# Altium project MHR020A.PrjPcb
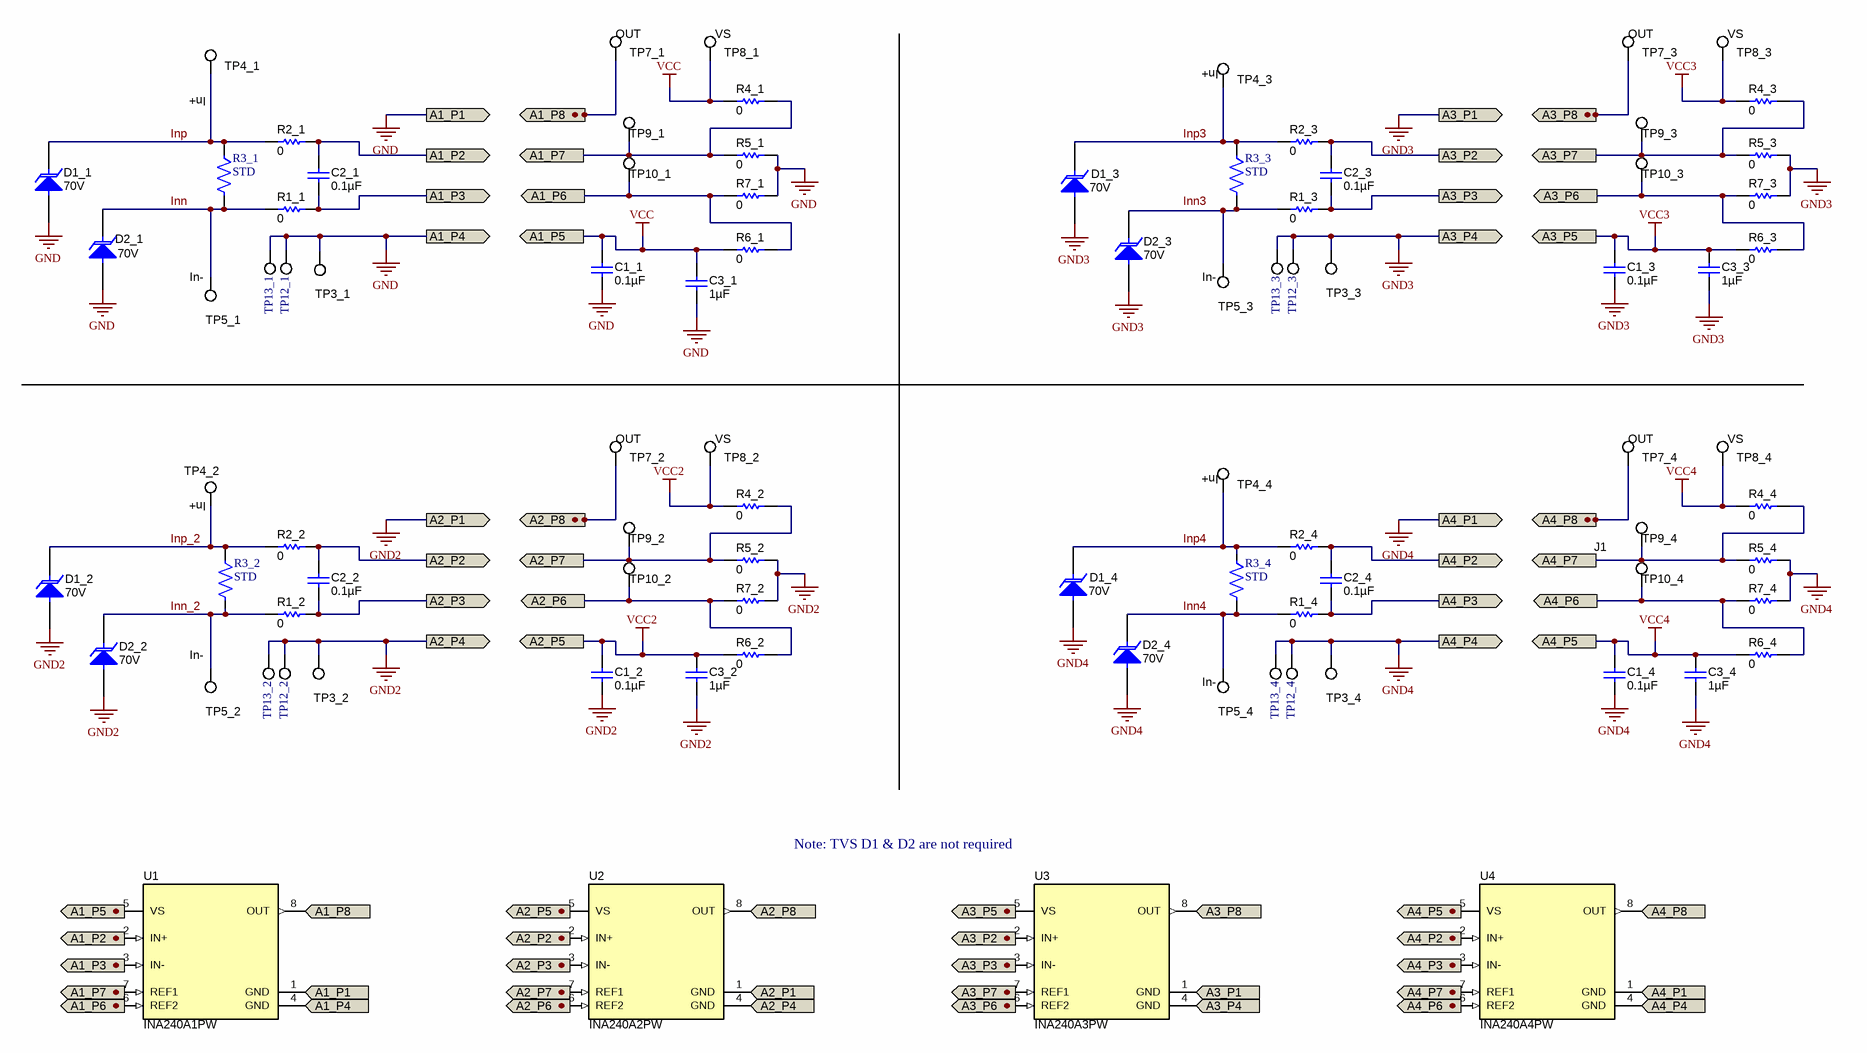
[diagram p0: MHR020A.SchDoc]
CopyrightYear: 2016; PCB_Layout: Guang Zhou; PCB_Rev: B; PRJ_Customer: Public; PRJ_Engineer: Guang Zhou; PRJ_Number: MHR020; PRJ_Title: INA240EVM; SCH_Rev: A; TechSupport: http://www.ti.com/support; TID: N/A
2 sheets, 119 parts. Net scope: flat (ports and power ports of the same name join across sheets).
Board file: MHR020B.PcbDoc
Sheets:
  MHR020A.SchDoc
  MHR020A_Hardware.SchDoc

## Sheet MHR020A.SchDoc: Schematic
size 431 x 279 mm; Date: Not shown in title block; ApprovedBy: Not shown in title block; CheckedBy: Not shown in title block; Author: Not shown in title block; CompanyName: Not shown in title block; DrawnBy: Guang Zhou; Engineer: Not shown in title block; Organization: Not shown in title block; Address1: Not shown in title block; Address2: Not shown in title block; Address3: Not shown in title block; Address4: Not shown in title block; DocumentNumber: 1; Revision: Use project parameter SCH_Rev; SheetNumber: 2; SheetTotal: 3; PageSetup: Record=PageOptions¦CenterHorizontal=True¦CenterVertical=True¦PrintScale=1.00¦XCorrection=1.00¦YCorrection=1.00¦PrintKind=0¦BorderSize=5000000¦LeftOffset=0¦BottomOffset=0¦Orientation=2¦PaperLength=1000¦PaperWidth=1000¦Scale=100¦PaperSource=15¦PrintQuality=600¦MediaType=1¦DitherType=10¦PaperKind=Letter¦PrintScaleMode=1

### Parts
C1_1  ValueDisplayed: 0.1µF  [0603]  (hidden comment: 0603YC104JAT2A)
C1_2  ValueDisplayed: 0.1µF  [0603]  (hidden comment: 0603YC104JAT2A)
C1_3  ValueDisplayed: 0.1µF  [0603]  (hidden comment: 0603YC104JAT2A)
C1_4  ValueDisplayed: 0.1µF  [0603]  (hidden comment: 0603YC104JAT2A)
C2_1  ValueDisplayed: 0.1µF  [0603]  (hidden comment: 0603YC104JAT2A)
C2_2  ValueDisplayed: 0.1µF  [0603]  (hidden comment: 0603YC104JAT2A)
C2_3  ValueDisplayed: 0.1µF  [0603]  (hidden comment: 0603YC104JAT2A)
C2_4  ValueDisplayed: 0.1µF  [0603]  (hidden comment: 0603YC104JAT2A)
C3_1  ValueDisplayed: 1µF  [0805_HV]  (hidden comment: 08053D105KAT2A)
C3_2  ValueDisplayed: 1µF  [0805_HV]  (hidden comment: 08053D105KAT2A)
C3_3  ValueDisplayed: 1µF  [0805_HV]  (hidden comment: 08053D105KAT2A)
C3_4  ValueDisplayed: 1µF  [0805_HV]  (hidden comment: 08053D105KAT2A)
D1_1  value 70V  [SMB]  (hidden comment: SMBJ70A-13-F)
D1_2  value 70V  [SMB]  (hidden comment: SMBJ70A-13-F)
D1_3  value 70V  [SMB]  (hidden comment: SMBJ70A-13-F)
D1_4  value 70V  [SMB]  (hidden comment: SMBJ70A-13-F)
D2_1  value 70V  [SMB]  (hidden comment: SMBJ70A-13-F)
D2_2  value 70V  [SMB]  (hidden comment: SMBJ70A-13-F)
D2_3  value 70V  [SMB]  (hidden comment: SMBJ70A-13-F)
D2_4  value 70V  [SMB]  (hidden comment: SMBJ70A-13-F)
R1_1  ValueDisplayed: 0  [0603]  (hidden comment: ERJ-3GEY0R00V)
R1_2  ValueDisplayed: 0  [0603]  (hidden comment: ERJ-3GEY0R00V)
R1_3  ValueDisplayed: 0  [0603]  (hidden comment: ERJ-3GEY0R00V)
R1_4  ValueDisplayed: 0  [0603]  (hidden comment: ERJ-3GEY0R00V)
R2_1  ValueDisplayed: 0  [0603]  (hidden comment: ERJ-3GEY0R00V)
R2_2  ValueDisplayed: 0  [0603]  (hidden comment: ERJ-3GEY0R00V)
R2_3  ValueDisplayed: 0  [0603]  (hidden comment: ERJ-3GEY0R00V)
R2_4  ValueDisplayed: 0  [0603]  (hidden comment: ERJ-3GEY0R00V)
R3_1  STD  [R2512]
R3_2  STD  [R2512]
R3_3  STD  [R2512]
R3_4  STD  [R2512]
R4_1  ValueDisplayed: 0  [0603]  (hidden comment: ERJ-3GEY0R00V)
R4_2  ValueDisplayed: 0  [0603]  (hidden comment: ERJ-3GEY0R00V)
R4_3  ValueDisplayed: 0  [0603]  (hidden comment: ERJ-3GEY0R00V)
R4_4  ValueDisplayed: 0  [0603]  (hidden comment: ERJ-3GEY0R00V)
R5_1  ValueDisplayed: 0  [0603]  (hidden comment: ERJ-3GEY0R00V)
R5_2  ValueDisplayed: 0  [0603]  (hidden comment: ERJ-3GEY0R00V)
R5_3  ValueDisplayed: 0  [0603]  (hidden comment: ERJ-3GEY0R00V)
R5_4  ValueDisplayed: 0  [0603]  (hidden comment: ERJ-3GEY0R00V)
R6_1  ValueDisplayed: 0  [0603]  (hidden comment: ERJ-3GEY0R00V)
R6_2  ValueDisplayed: 0  [0603]  (hidden comment: ERJ-3GEY0R00V)
R6_3  ValueDisplayed: 0  [0603]  (hidden comment: ERJ-3GEY0R00V)
R6_4  ValueDisplayed: 0  [0603]  (hidden comment: ERJ-3GEY0R00V)
R7_1  ValueDisplayed: 0  [0603]  (hidden comment: ERJ-3GEY0R00V)
R7_2  ValueDisplayed: 0  [0603]  (hidden comment: ERJ-3GEY0R00V)
R7_3  ValueDisplayed: 0  [0603]  (hidden comment: ERJ-3GEY0R00V)
R7_4  ValueDisplayed: 0  [0603]  (hidden comment: ERJ-3GEY0R00V)
TP3_1  5012  [Keystone5012]  (value not drawn)
TP3_2  5012  [Keystone5012]  (value not drawn)
TP3_3  5012  [Keystone5012]  (value not drawn)
TP3_4  5012  [Keystone5012]  (value not drawn)
TP4_1  5012  [Keystone5012]  (value not drawn)
TP4_2  5012  [Keystone5012]  (value not drawn)
TP4_3  5012  [Keystone5012]  (value not drawn)
TP4_4  5012  [Keystone5012]  (value not drawn)
TP5_1  5012  [Keystone5012]  (value not drawn)
TP5_2  5012  [Keystone5012]  (value not drawn)
TP5_3  5012  [Keystone5012]  (value not drawn)
TP5_4  5012  [Keystone5012]  (value not drawn)
TP7_1  5012  [Keystone5012]  (value not drawn)
TP7_2  5012  [Keystone5012]  (value not drawn)
TP7_3  5012  [Keystone5012]  (value not drawn)
TP7_4  5012  [Keystone5012]  (value not drawn)
TP8_1  5012  [Keystone5012]  (value not drawn)
TP8_2  5012  [Keystone5012]  (value not drawn)
TP8_3  5012  [Keystone5012]  (value not drawn)
TP8_4  5012  [Keystone5012]  (value not drawn)
TP9_1  5012  [Keystone5012]  (value not drawn)
TP9_2  5012  [Keystone5012]  (value not drawn)
TP9_3  5012  [Keystone5012]  (value not drawn)
TP9_4  5012  [Keystone5012]  (value not drawn)
TP10_1  5012  [Keystone5012]  (value not drawn)
TP10_2  5012  [Keystone5012]  (value not drawn)
TP10_3  5012  [Keystone5012]  (value not drawn)
TP10_4  5012  [Keystone5012]  (value not drawn)
TP12_1  5012  [Keystone5012]  (value not drawn)
TP12_2  5012  [Keystone5012]  (value not drawn)
TP12_3  5012  [Keystone5012]  (value not drawn)
TP12_4  5012  [Keystone5012]  (value not drawn)
TP13_1  5012  [Keystone5012]  (value not drawn)
TP13_2  5012  [Keystone5012]  (value not drawn)
TP13_3  5012  [Keystone5012]  (value not drawn)
TP13_4  5012  [Keystone5012]  (value not drawn)
U1  INA240A1PW  [PW0008A_N]
U2  INA240A2PW  [PW0008A_N]
U3  INA240A3PW  [PW0008A_N]
U4  INA240A4PW  [PW0008A_N]

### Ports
A1_P1 (in), A1_P1 (out), A1_P2 (in), A1_P2 (out), A1_P3 (in), A1_P3 (out), A1_P4 (in), A1_P4 (out), A1_P5 (in), A1_P5 (out), A1_P6 (in), A1_P6 (out), A1_P7 (in), A1_P7 (out), A1_P8 (in), A1_P8 (out), A2_P1 (in), A2_P1 (out), A2_P2 (in), A2_P2 (out), A2_P3 (in), A2_P3 (out), A2_P4 (in), A2_P4 (out), A2_P5 (in), A2_P5 (out), A2_P6 (in), A2_P6 (out), A2_P7 (in), A2_P7 (out), A2_P8 (in), A2_P8 (out), A3_P1 (in), A3_P1 (out), A3_P2 (in), A3_P2 (out), A3_P3 (in), A3_P3 (out), A3_P4 (in), A3_P4 (out), A3_P5 (in), A3_P5 (out), A3_P6 (in), A3_P6 (out), A3_P7 (in), A3_P7 (out), A3_P8 (in), A3_P8 (out), A4_P1 (in), A4_P1 (out), A4_P2 (in), A4_P2 (out), A4_P3 (in), A4_P3 (out), A4_P4 (in), A4_P4 (out), A4_P5 (in), A4_P5 (out), A4_P6 (in), A4_P6 (out), A4_P7 (in), A4_P7 (out), A4_P8 (in), A4_P8 (out)

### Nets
GND: C1_1.2 C3_1.2 D1_1.2(A) D2_1.2(A) R5_1.2 R7_1.2 TP3_1.1 TP12_1.1 TP13_1.1 U1.1(GND) U1.4(GND) ; port A1_P1, port A1_P4
GND2: C1_2.2 C3_2.2 D1_2.2(A) D2_2.2(A) R5_2.2 R7_2.2 TP3_2.1 TP12_2.1 TP13_2.1 U2.1(GND) U2.4(GND) ; port A2_P1, port A2_P4
GND3: C1_3.2 C3_3.2 D1_3.2(A) D2_3.2(A) R5_3.2 R7_3.2 TP3_3.1 TP12_3.1 TP13_3.1 U3.1(GND) U3.4(GND) ; port A3_P1, port A3_P4
GND4: C1_4.2 C3_4.2 D1_4.2(A) D2_4.2(A) R5_4.2 R7_4.2 TP3_4.1 TP12_4.1 TP13_4.1 U4.1(GND) U4.4(GND) ; port A4_P1, port A4_P4
VCC: C1_1.1 C3_1.1 R4_1.1 R6_1.1 TP8_1.1 ; port A1_P5
VCC2: C1_2.1 C3_2.1 R4_2.1 R6_2.1 TP8_2.1 ; port A2_P5
VCC3: C1_3.1 C3_3.1 R4_3.1 R6_3.1 TP8_3.1 ; port A3_P5
VCC4: C1_4.1 C3_4.1 R4_4.1 R6_4.1 TP8_4.1 ; port A4_P5
A1_P2: C2_1.2 R2_1.2 ; port A1_P2
A1_P3: C2_1.1 R1_1.2 ; port A1_P3
A1_P6: R6_1.2 R7_1.1 TP10_1.1 ; port A1_P6
A1_P7: R4_1.2 R5_1.1 TP9_1.1 ; port A1_P7
A1_P8: TP7_1.1 U1.8(OUT) ; port A1_P8
A2_P2: C2_2.2 R2_2.2 ; port A2_P2
A2_P3: C2_2.1 R1_2.2 ; port A2_P3
A2_P6: R6_2.2 R7_2.1 TP10_2.1 ; port A2_P6
A2_P7: R4_2.2 R5_2.1 TP9_2.1 ; port A2_P7
A2_P8: TP7_2.1 U2.8(OUT) ; port A2_P8
A3_P2: C2_3.2 R2_3.2 ; port A3_P2
A3_P3: C2_3.1 R1_3.2 ; port A3_P3
A3_P6: R6_3.2 R7_3.1 TP10_3.1 ; port A3_P6
A3_P7: R4_3.2 R5_3.1 TP9_3.1 ; port A3_P7
A3_P8: TP7_3.1 U3.8(OUT) ; port A3_P8
A4_P2: C2_4.2 R2_4.2 ; port A4_P2
A4_P3: C2_4.1 R1_4.2 ; port A4_P3
A4_P6: R6_4.2 R7_4.1 TP10_4.1 ; port A4_P6
A4_P7: R4_4.2 R5_4.1 TP9_4.1 ; port A4_P7
A4_P8: TP7_4.1 U4.8(OUT) ; port A4_P8
Inn: D2_1.1(K) R1_1.1 R3_1.2 TP5_1.1
Inn4: D2_4.1(K) R1_4.1 R3_4.2 TP5_4.1
Inn_2: D2_2.1(K) R1_2.1 R3_2.2 TP5_2.1
Inp: D1_1.1(K) R2_1.1 R3_1.1 TP4_1.1
Inp3: D1_3.1(K) R2_3.1 R3_3.1 TP4_3.1
Inp4: D1_4.1(K) R2_4.1 R3_4.1 TP4_4.1
Inp_2: D1_2.1(K) R2_2.1 R3_2.1 TP4_2.1
NetD2_3_1: D2_3.1(K) R1_3.1 R3_3.2 TP5_3.1

Not connected (* = marked no-connect by the designer): U1 2(IN+) 3(IN-) 5(VS) 6(REF2) 7(REF1); U2 2(IN+) 3(IN-) 5(VS) 6(REF2) 7(REF1); U3 2(IN+) 3(IN-) 5(VS) 6(REF2) 7(REF1); U4 2(IN+) 3(IN-) 5(VS) 6(REF2) 7(REF1)

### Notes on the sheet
- (near TP7_1) OUT
- (near TP8_1) VS
- (near TP4_3) In+
- (near TP7_3) OUT
- (near TP8_3) VS
- In+
- (near TP5_1) In-
- (near TP5_3) In-
- (near TP7_2) OUT
- (near TP8_2) VS
- (near TP4_4) In+
- (near TP7_4) OUT
- (near TP8_4) VS
- (near TP4_2) In+
- J1
- (near TP5_2) In-
- (near TP5_4) In-
- Note: TVS D1 & D2 are not required
- Labels drawn without touching a wire or pin: Inn3

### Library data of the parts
C1_1-C1_4 C2_1-C2_4 = 0603YC104JAT2A: CAP, CERM, 0.1 µF, 16 V, +/- 5%, X7R, 0603; Manufacturer: AVX; Polarized: N; CompType: Capacitor; Value: 0.1uF; U/M: EA; Cap_F: 0.0000001; Tolerance_%: 5; ESR_ohm: 0.039; Value1: 0.039 ohm; VDC_V: 16; Value2: 16V; TaMin_C: -55; TaMax_C: 125
C3_1-C3_4 = 08053D105KAT2A: CAP, CERM, 1 µF, 25 V, +/- 10%, X5R, 0805; Manufacturer: AVX; Polarized: N; CompType: Capacitor; Value: 1uF; U/M: EA; Cap_F: 0.000001; Tolerance_%: 10; ESR_ohm: 0.012; Value1: 0.012 ohm; VDC_V: 25; Value2: 25V; TaMin_C: -55; TaMax_C: 85; Cap_Case: 0805; AEC Category: Q200
D1_1-D1_4 D2_1-D2_4 = SMBJ70A-13-F: Diode, TVS, Uni, 70 V, 600 W, SMB; Manufacturer: Diodes Inc.; U/M: EA; Power_W: 5; Vr_V: 70; Value1: 5W; AEC Category: Q101
R1_1-R1_4 R2_1-R2_4 R4_1-R4_4 R5_1-R5_4 R6_1-R6_4 R7_1-R7_4 = ERJ-3GEY0R00V: RES, 0, 5%, 0.1 W, 0603; Manufacturer: Panasonic; CompType: Resistor; Value: 0; Value_Code: 0000; Tolerance_%: 5; Power_W: 0.1; Value2: 0.1W; VDC_V: 50; TempCo: 600 ppm/C; EIA_Code: E24; U/M: EA; AEC Category: Q200
R3_1-R3_4 = R2512: Resistor,  xx milliOhm, 1W, yy%; Area: 35100; Value: {Value}
TP3_1-TP3_4 TP4_1-TP4_4 TP5_1-TP5_4 TP7_1-TP7_4 TP8_1-TP8_4 TP9_1-TP9_4 TP10_1-TP10_4 = 5012: Test Point, Multipurpose, White, TH; Manufacturer: Keystone; CompType: Test Point Loop; U/M: EA
TP12_1-TP12_4 TP13_1-TP13_4 = 5012: Test Point, Multipurpose, White, TH; Manufacturer: Keystone; CompType: Test Point Loop; ContactFinish: Silver
U1 = INA240A1PW: Wide Common-Mode Range, Voltage Output, High or Low-Side Bi-Directional Zero-Drift Current Shunt Monitor, PW0008A; Manufacturer: Texas Instruments; SymbolCreator: Altium; CompType: IC; U/M: EA
U2 = INA240A2PW: Wide Common-Mode Range, Voltage Output, High or Low-Side Bi-Directional Zero-Drift Current Shunt Monitor, PW0008A; Manufacturer: Texas Instruments; SymbolCreator: Altium; CompType: IC; U/M: EA
U3 = INA240A3PW: Wide Common-Mode Range, Voltage Output, High or Low-Side Bi-Directional Zero-Drift Current Shunt Monitor, PW0008A; Manufacturer: Texas Instruments; SymbolCreator: Altium; CompType: IC; U/M: EA
U4 = INA240A4PW: Wide Common-Mode Range, Voltage Output, High or Low-Side Bi-Directional Zero-Drift Current Shunt Monitor, PW0008A; Manufacturer: Texas Instruments; SymbolCreator: Altium; CompType: IC; U/M: EA

## Sheet MHR020A_Hardware.SchDoc: Hardware
size 431 x 279 mm; Date: Not shown in title block; ApprovedBy: Not shown in title block; CheckedBy: Not shown in title block; Author: Not shown in title block; CompanyName: Not shown in title block; DrawnBy: Guang Zhou; Engineer: Not shown in title block; Organization: Not shown in title block; Address1: Not shown in title block; Address2: Not shown in title block; Address3: Not shown in title block; Address4: Not shown in title block; DocumentNumber: 1; Revision: Use project parameter SCH_Rev; SheetNumber: 3; SheetTotal: 3; PageSetup: Record=PageOptions¦CenterHorizontal=True¦CenterVertical=True¦PrintScale=1.00¦XCorrection=1.00¦YCorrection=1.00¦PrintKind=0¦BorderSize=5000000¦LeftOffset=0¦BottomOffset=0¦Orientation=2¦PaperLength=1000¦PaperWidth=1000¦Scale=100¦PaperSource=15¦PrintQuality=600¦MediaType=1¦DitherType=10¦PaperKind=Letter¦PrintScaleMode=1
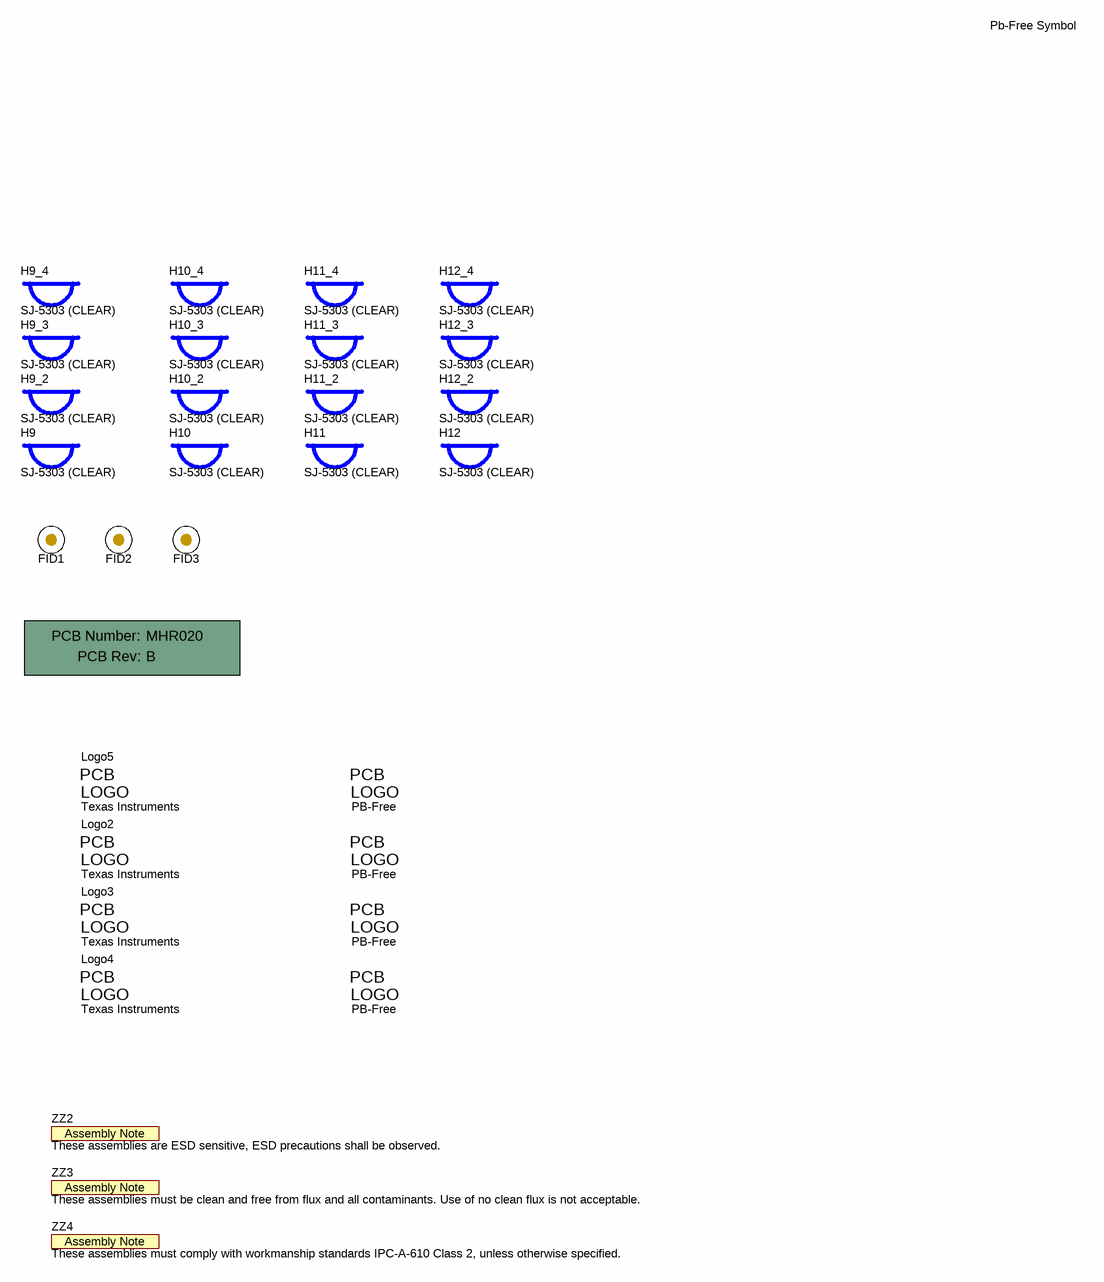
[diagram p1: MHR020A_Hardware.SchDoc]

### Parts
(Parts that share a designator on the sheet are numbered #1, #2 ... from top to bottom, then left to right.)
!PCB  Printed Circuit Board  (value not drawn)  (mechanical)
FID1  Fiducial  [Fiducial10-20]  (value not drawn)
FID2  Fiducial  [Fiducial10-20]  (value not drawn)
FID3  Fiducial  [Fiducial10-20]  (value not drawn)
H9  SJ-5303 (CLEAR)  [Bumpon_SJ5003Transparent]
H9_2  SJ-5303 (CLEAR)  [Bumpon_SJ5003Transparent]
H9_3  SJ-5303 (CLEAR)  [Bumpon_SJ5003Transparent]
H9_4  SJ-5303 (CLEAR)  [Bumpon_SJ5003Transparent]
H10  SJ-5303 (CLEAR)  [Bumpon_SJ5003Transparent]
H10_2  SJ-5303 (CLEAR)  [Bumpon_SJ5003Transparent]
H10_3  SJ-5303 (CLEAR)  [Bumpon_SJ5003Transparent]
H10_4  SJ-5303 (CLEAR)  [Bumpon_SJ5003Transparent]
H11  SJ-5303 (CLEAR)  [Bumpon_SJ5003Transparent]
H11_2  SJ-5303 (CLEAR)  [Bumpon_SJ5003Transparent]
H11_3  SJ-5303 (CLEAR)  [Bumpon_SJ5003Transparent]
H11_4  SJ-5303 (CLEAR)  [Bumpon_SJ5003Transparent]
H12  SJ-5303 (CLEAR)  [Bumpon_SJ5003Transparent]
H12_2  SJ-5303 (CLEAR)  [Bumpon_SJ5003Transparent]
H12_3  SJ-5303 (CLEAR)  [Bumpon_SJ5003Transparent]
H12_4  SJ-5303 (CLEAR)  [Bumpon_SJ5003Transparent]
Logo2  Texas Instruments  [TI_Stacked_Overlay_Small]  (no BOM)
Logo3  Texas Instruments  [TI_Stacked_Overlay_Small]  (no BOM)
Logo4  Texas Instruments  [TI_Stacked_Overlay_Small]  (no BOM)
Logo5  Texas Instruments  [TI_Stacked_Overlay_Small]  (no BOM)
PB-Free#1  Pb-Free Symbol  [Pb-Free_Overlay_Small]  (no BOM)
PB-Free#2  Pb-Free Symbol  [Pb-Free_Overlay_Small]  (value not drawn)  (no BOM)
PB-Free#3  Pb-Free Symbol  [Pb-Free_Overlay_Small]  (value not drawn)  (no BOM)
PB-Free#4  Pb-Free Symbol  [Pb-Free_Overlay_Small]  (value not drawn)  (no BOM)
ZZ2  These assemblies are ESD sensitive, ESD precautions shall be observed.  [AssemblyNote]  (no BOM)
ZZ3  These assemblies must be clean and free from flux and all contaminants. Use of no clean flux is not acceptable.  [AssemblyNote]  (no BOM)
ZZ4  These assemblies must comply with workmanship standards IPC-A-610 Class 2, unless otherwise specified.  [AssemblyNote]  (no BOM)

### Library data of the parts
!PCB = PCB: Manufacturer: Any; PartNumber: MHR020; SymbolCreator: a0412235
FID1-FID3 = Fiducial: Fiducial mark.  There is nothing to buy or mount.; SymbolCreator: codlsc
H9 H9_2-H9_4 H10 H10_2-H10_4 H11 H11_2-H11_4 H12 H12_2-H12_4 = SJ-5303 (CLEAR): Bumpon, Hemisphere, 0.44 X 0.20, Clear; Manufacturer: 3M; SymbolCreator: a0412235
Logo2-Logo5 = TI_Logo: Texas Instrument Corporate Signature; SymbolCreator: a0412235
PB-Free#1-PB-Free#4 = Pb-Free: SymbolCreator: a0412235
ZZ2-ZZ4 = AssemblyNote: SymbolCreator: codlsc

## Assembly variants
001: not fitted C2_1 C2_2 C2_3 C2_4 FID1 FID2 FID3 H12_4 R3_1 R3_2 R3_3 R3_4 R5_1 R5_2 R5_3 R5_4 R6_1 R6_2 R6_3 R6_4 TP3_1 TP3_2 TP3_3 TP3_4 TP4_1 TP4_2 TP4_3 TP4_4 TP5_1 TP5_2 TP5_3 TP5_4 TP7_1 TP7_2 TP7_3 TP7_4 TP8_1 TP8_2 TP8_3 TP8_4 TP9_1 TP9_2 TP9_3 TP9_4 TP10_1 TP10_2 TP10_3 TP10_4 TP11_1 TP11_2 TP11_3 TP11_4 TP12_1 TP12_2 TP12_3 TP12_4 TP13_1 TP13_2 TP13_3 TP13_4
